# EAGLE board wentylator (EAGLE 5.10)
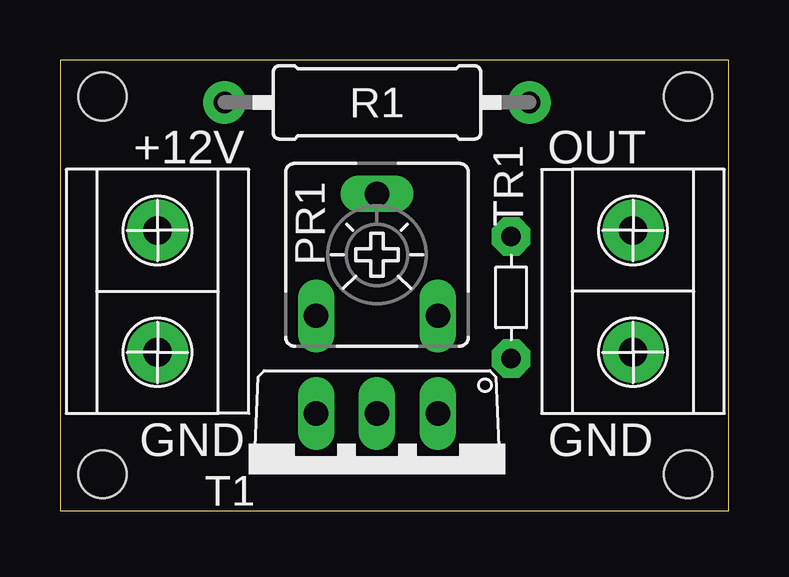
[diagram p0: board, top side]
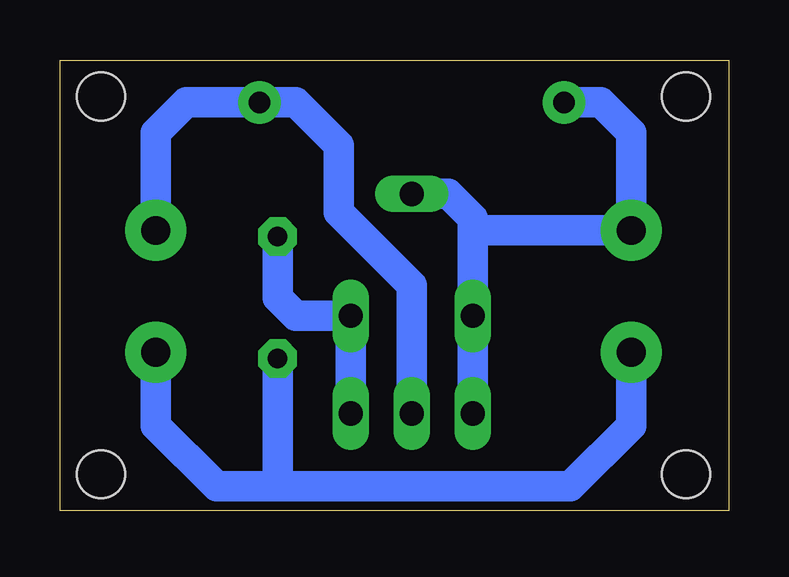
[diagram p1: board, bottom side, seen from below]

Size 27.86 x 18.79 mm. Coordinates in mm from the lower left corner, seen from the top.
Outline: 0,0 27.86,0 27.86,18.79 0,18.79 0,0
Copper layers (1*16): Top 0.035mm / dielectric 1.5mm / Bottom 0.035mm
Design rules "default": minimum track width 10mil, minimum drill 24mil, track to track 8mil, track to pad 8mil, pad to pad 8mil, via to via 8mil, smd to smd 8mil, copper to edge 40mil, drill to drill 8mil, minimum pad ring 10mil, minimum via ring 8mil, stop-mask expansion 4mil, vias tented up to drill 0mil, thermal gap 10mil
Holes 2 mm at 1.78,1.52 26.16,1.52 1.78,17.27 26.16,17.27

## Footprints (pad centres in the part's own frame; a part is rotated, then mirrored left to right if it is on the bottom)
CA6V = drill 1.016 long: A -2.54,-2.54; E 2.54,-2.54; S 0,2.54
0309/12 = drill 0.813 octagon: 1 -6.35,0; 2 6.35,0
TO220V = drill 1.016 long: 1 -2.54,-2.54; 2 0,-2.54; 3 2.54,-2.54
R-5 = drill 0.813 pad 1.6 octagon: 1 -2.54,0; 2 2.54,0
ARK2 = drill 1.2 pad 2.54 round: 1 -2.54,0; 3 2.54,0 | drill 0.8 pad 2.54 round: 2 2.54,0

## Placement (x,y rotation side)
PR1  [CA6V]  13.21,10.67 0 top
R1  [0309/12]  13.21,17.02 180 top
T1  IRF9530220V  [TO220V]  13.21,1.52 180 top
TR1  [R-5]  18.8,8.89 270 top
U$1  ARK2  [ARK2]  23.88,9.14 90 top
U$2  ARK2  [ARK2]  4.06,9.14 270 top

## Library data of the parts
PR1 = pot
R1 = resistor
T1 = transistor-fet
TR1 = discrete
U$1 U$2 = ark2

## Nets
N$1: PR1.E T1.1 TR1.1
N$3: TR1.2 U$1.1 U$2.2
N$4: PR1.A PR1.S R1.2 T1.3 U$2.1
N$5: R1.1 T1.2 U$1.2

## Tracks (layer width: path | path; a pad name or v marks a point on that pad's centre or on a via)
N$1
  Bottom 1.27: T1.1 PR1.E 18.03,8.13 18.8,8.89 TR1.1
N$2  (via drill 0.9 pad 1.78)
  other vias: 6.86,17.02
N$3
  Bottom 1.27: U$2.2 4.06,3.56 6.6,1.02 18.8,1.02 | 18.8,1.02 21.34,1.02 23.88,3.56 U$1.1 | 18.8,1.02 TR1.2
N$4
  Bottom 1.27: T1.3 PR1.A | R1.2 5.33,17.02 4.06,15.75 U$2.1 10.67,11.68 | PR1.A 10.67,8.64 | PR1.A 10.67,11.68 | 10.67,11.68 10.67,12.19 11.68,13.21 PR1.S
N$5
  Bottom 1.27: U$1.2 23.88,15.75 22.61,17.02 R1.1 18.03,17.02 16.26,15.24 16.26,12.45 13.21,9.4 T1.2
N$6  (via drill 0.9 pad 1.78)
  other vias: 19.56,17.02

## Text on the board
tNames: +12V | OUT | GND | GND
